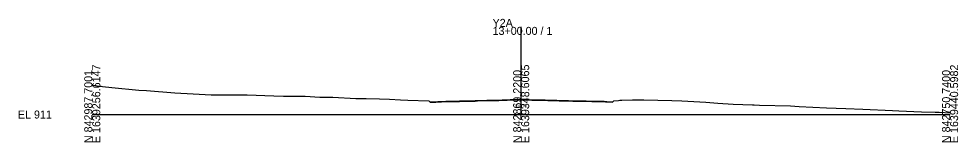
# Model space of a CAD drawing. Extents: x -26 to 303, y -10 to 10517.
# Drawn here: x -25.7 to 302.8, y 2490.3 to 2533.5 of the extents above; entities that cross this region are included whole.
import ezdxf

# ---------------------------------------------------------------- set-up
doc = ezdxf.new("R2010")
doc.units = 0
for name, color, linetype in [('Exist Cross Section Cell', 7, 'Continuous'), ('Exist XS Center Line Elevation Label', 7, 'Continuous'), ('Exist XS Ground Line', 7, 'Continuous'), ('Prop CMT Pvmt Surface Overlay', 7, 'Continuous')]:
    doc.layers.add(name, color=color, linetype=linetype)

msp = doc.modelspace()

# ---------------------------------------------------------------- linework, layer by layer
at = {"layer": 'Exist Cross Section Cell'}
for p, q in [((150, 2500), (150, 2530.67)), ((0, 2500), (150, 2500)), ((150, 2500), (300, 2500))]:
    msp.add_line(p, q, dxfattribs=at)
at = {"layer": 'Exist XS Ground Line'}
msp.add_lwpolyline([(0, 2510.22), (2.64, 2509.92), (3.17, 2509.87), (3.58, 2509.82), (6.85, 2509.48), (16.24, 2508.56), (18.94, 2508.35), (28.9, 2507.59), (35.25, 2507.23), (41.56, 2506.94), (51.56, 2506.9), (53.06, 2506.92), (54.22, 2506.87), (63.48, 2506.56), (66.88, 2506.44), (67.31, 2506.44), (67.86, 2506.43), (74.44, 2506.45), (79.55, 2506.09), (84.17, 2506.03), (92.21, 2505.66), (95.82, 2505.61), (100.48, 2505.48), (103.96, 2505.38), (107.78, 2505.17), (110.4, 2505.07), (117.71, 2504.8), (118.15, 2504.33), (119.43, 2504.35), (120.1, 2504.37), (120.91, 2504.41), (122.11, 2504.47), (123.71, 2504.52), (125.27, 2504.56), (125.78, 2504.57), (128.44, 2504.61), (129.85, 2504.64), (131.64, 2504.69), (132.34, 2504.71), (133.93, 2504.73), (134.77, 2504.75), (138, 2504.87), (141.1, 2504.92), (142.24, 2504.96), (143.34, 2504.99), (144.26, 2505.01), (145.09, 2505.04), (146.16, 2505.09), (147.43, 2505.13), (148.86, 2505.14), (150, 2505.13), (150.6, 2505.13), (152.22, 2505.1), (153.76, 2505.07), (154.31, 2505.06), (155.45, 2505.04), (157.01, 2505.01), (158.39, 2504.99), (159.35, 2504.94), (160.09, 2504.92), (162.46, 2504.86), (163.26, 2504.83), (164.69, 2504.79), (166.52, 2504.75), (168.04, 2504.72), (169.59, 2504.68), (170.62, 2504.66), (172.75, 2504.62), (174.69, 2504.59), (175.92, 2504.56), (179.02, 2504.51), (179.47, 2504.48), (179.92, 2504.45), (181.95, 2504.36), (182.44, 2504.82), (183.99, 2504.95), (184.5, 2505), (185.23, 2505.06), (188.88, 2505.15), (189.42, 2505.16), (192.91, 2505.09), (202.73, 2504.94), (206.16, 2504.76), (214.62, 2504.28), (218.82, 2504.01), (224.11, 2503.64), (230.93, 2503.41), (231.48, 2503.39), (233.38, 2503.33), (244.14, 2503), (247.24, 2502.86), (256.8, 2502.4), (263.54, 2502.09), (269.46, 2501.86), (279.85, 2501.39), (282.12, 2501.29), (290.01, 2501), (294.79, 2500.82), (296.16, 2500.77), (300, 2500.64)], dxfattribs=at)
at = {"layer": 'Prop CMT Pvmt Surface Overlay'}
msp.add_lwpolyline([(118.04, 2504.45), (119.43, 2504.48), (120.09, 2504.49), (120.9, 2504.54), (122.1, 2504.6), (123.71, 2504.64), (125.27, 2504.68), (125.77, 2504.69), (128.44, 2504.74), (129.85, 2504.77), (131.64, 2504.81), (132.34, 2504.83), (133.93, 2504.86), (134.77, 2504.87), (138, 2505), (141.1, 2505.05), (142.24, 2505.08), (143.34, 2505.11), (144.26, 2505.14), (145.09, 2505.16), (146.15, 2505.21), (147.43, 2505.25), (148.86, 2505.26), (150, 2505.26), (150.6, 2505.26), (152.22, 2505.23), (153.76, 2505.2), (154.31, 2505.19), (155.45, 2505.16), (157.01, 2505.13), (158.39, 2505.11), (159.35, 2505.06), (160.09, 2505.05), (162.47, 2504.98), (163.26, 2504.96), (164.69, 2504.91), (166.52, 2504.87), (168.05, 2504.84), (169.59, 2504.81), (170.62, 2504.79), (172.75, 2504.75), (174.7, 2504.71), (175.92, 2504.69), (179.02, 2504.63), (179.47, 2504.6), (179.93, 2504.58), (182.07, 2504.48)], dxfattribs=at)

# ---------------------------------------------------------------- texts
at = {"layer": 'Exist Cross Section Cell'}
for s, p in [('Y2A', (140, 2530.67)), ('13+00.00 / 1', (140, 2527.87)), ('EL 911', (-26, 2498.6))]:
    msp.add_text(s, height=2.8, dxfattribs=at).set_placement(p)
for s, p in [('E 1639256.6147', (2.8, 2490)), ('E 1639348.6065', (152.8, 2490)), ('E 1639440.5982', (302.8, 2490)), ('N 842987.7001', (0, 2490)), ('N 842869.2200', (150, 2490)), ('N 842750.7400', (300, 2490))]:
    msp.add_text(s, height=2.8, rotation=90, dxfattribs=at).set_placement(p)
at = {"layer": 'Exist XS Center Line Elevation Label'}
msp.add_text('916.13', height=1, dxfattribs=at).set_placement((147.77, 2502.46))

doc.saveas('drawing.dxf')
